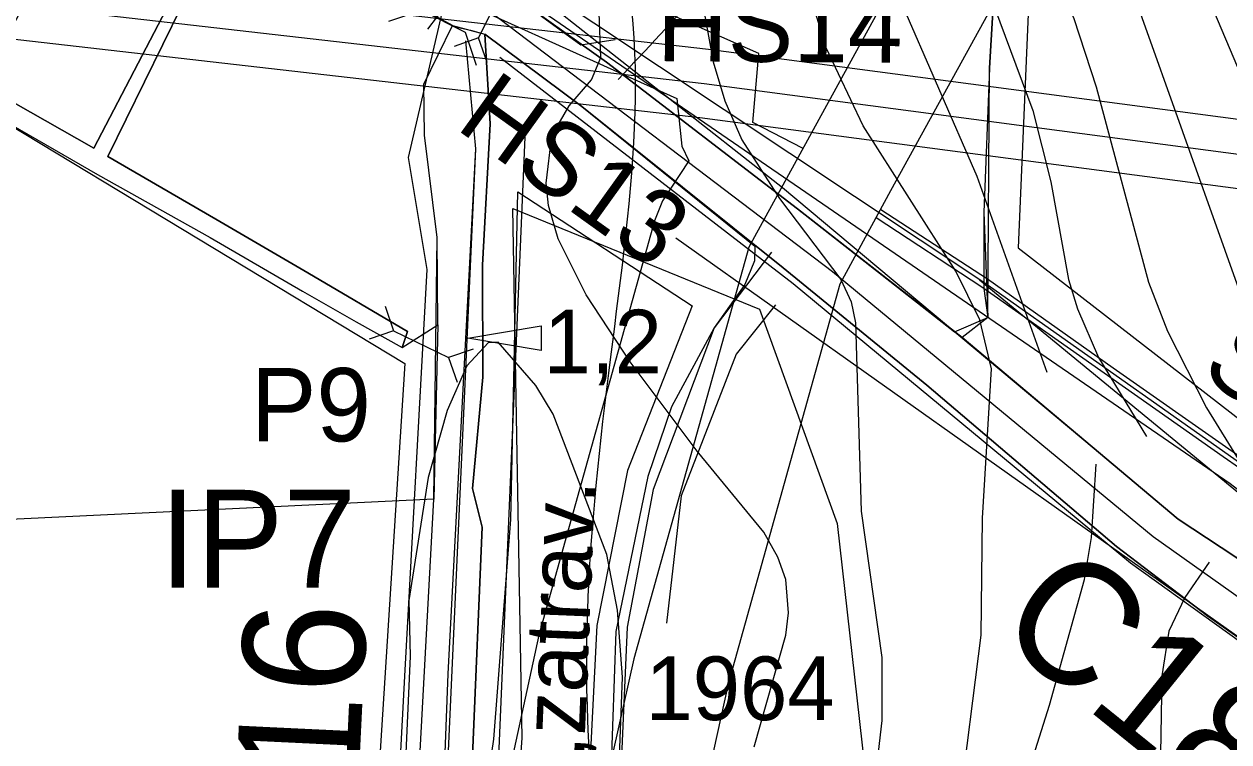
# Model space of a CAD drawing. Extents: x -684583 to -680383, y -1157874 to -1154904.
# Drawn here: x -683041.8 to -682795.6, y -1157173.5 to -1157026.8 of the extents above; entities that cross this region are included whole.
import ezdxf

# ---------------------------------------------------------------- set-up
doc = ezdxf.new("R2010")
doc.units = 0
for name, color, linetype in [('01_PRVKY PRŮZKUMU', 7, 'Continuous'), ('01_PRVKY PSZ', 7, 'Continuous'), ('01_VRSTEVNICE', 7, 'Continuous'), ('02_KULTURY NÁVRH', 7, 'Continuous'), ('02_KULTURY STAV', 7, 'Continuous'), ('03_PC_NÁVRH', 7, 'Continuous'), ('03_PC_OBJEKTY_NÁVRH', 7, 'Continuous'), ('03_PC_OBJEKTY_STAV', 7, 'Continuous'), ('03_PC_POPIS_STAV', 7, 'Continuous'), ('03_PC_STAV', 7, 'Continuous'), ('04_ZPF_OP_ORGAN', 7, 'Continuous'), ('05_VHO_MELIORACE', 7, 'Continuous'), ('05_VHO_V_TOK', 7, 'Continuous'), ('06_BIOGEOGRAFIE', 7, 'Continuous'), ('06_ÚSES_IP', 7, 'Continuous'), ('07_ELEKTRO', 7, 'Continuous'), ('07_OCH_P A POPISY TI', 7, 'Continuous'), ('07_PLYNOVOD', 7, 'Continuous'), ('07_VODOVOD', 7, 'Continuous')]:
    doc.layers.add(name, color=color, linetype=linetype)

msp = doc.modelspace()

# ---------------------------------------------------------------- linework, layer by layer
at = {"layer": '01_PRVKY PRŮZKUMU'}
msp.add_lwpolyline([(-683079.01, -1157360), (-683101.29, -1157316.95), (-683114.85, -1157271.95), (-683118.75, -1157234.34), (-683126.76, -1157209.48), (-683135.39, -1157142.69), (-683125.32, -1157092.55), (-683090.58, -1157019.64), (-682963.99, -1157096.18), (-682973.33, -1157242.9), (-682974.69, -1157258.59), (-682742.08, -1157344.31)], dxfattribs=at)
at = {"layer": '01_PRVKY PSZ'}
msp.add_lwpolyline([(-682951.59, -1157030.23), (-682949.58, -1157052.3), (-682959.2, -1157265.52), (-682962.61, -1157285.78), (-682967.05, -1157374.21), (-682960.06, -1157422.81), (-682935.41, -1157484.7), (-682916.27, -1157543.42), (-682905.44, -1157579.25), (-682923.84, -1157669.47), (-682932.49, -1157713.29), (-682940.15, -1157759.63), (-682931.41, -1157813.92)], dxfattribs=at)
at = {"layer": '01_VRSTEVNICE'}
for points in [[(-682847.51, -1156890.14), (-682852.36, -1156911.54), (-682852.5, -1156920.1), (-682851.64, -1156928.65), (-682847.94, -1156945.77), (-682843.51, -1156958.61), (-682823.4, -1157000.55), (-682813.7, -1157024.51), (-682787.74, -1157097.26)], [(-682829.39, -1156891.85), (-682832.67, -1156900.98), (-682834.1, -1156907.83), (-682834.38, -1156923.8), (-682833.24, -1156935.22), (-682831.39, -1156944.34), (-682827.68, -1156955.76), (-682811.13, -1156992.56), (-682800.43, -1157019.95), (-682783.03, -1157061.03)], [(-682866.62, -1156893.42), (-682865.91, -1156914.39), (-682866.91, -1156948.62), (-682866.05, -1156957.75), (-682852.64, -1156998.83), (-682835.67, -1157044.48), (-682831.96, -1157059.03), (-682828.39, -1157079), (-682826.54, -1157084.99), (-682822.26, -1157094.98), (-682812.42, -1157111.1)], [(-682859.35, -1156895.28), (-682860.06, -1156910.68), (-682859.92, -1156928.65), (-682858.78, -1156943.49), (-682855.64, -1156957.18), (-682852.07, -1156969.16), (-682847.08, -1156982.86), (-682835.24, -1157006.82), (-682827.25, -1157025.65), (-682822.69, -1157039.63), (-682811.99, -1157079.57), (-682808.14, -1157089.56), (-682800.15, -1157105.25), (-682793.16, -1157116.66)], [(-682954.57, -1156992.15), (-682947.79, -1156992.56), (-682940.8, -1156990.71), (-682933.52, -1156986.42), (-682927.25, -1156980.58), (-682916.26, -1156967.45), (-682911.7, -1156963.32), (-682907.85, -1156962.75), (-682902.43, -1156968.88), (-682903, -1156977.44), (-682904.85, -1156986), (-682904.71, -1156998.55), (-682903.14, -1157022.51), (-682901, -1157034.5), (-682898.57, -1157042.48), (-682895.15, -1157050.47), (-682887.45, -1157062.46), (-682874.9, -1157079), (-682872.76, -1157083.57), (-682871.9, -1157087.84), (-682870.76, -1157126.36), (-682866.48, -1157156.31), (-682866.48, -1157169.15), (-682867.48, -1157177.43)], [(-682933.95, -1157049.62), (-682930.38, -1157043.48), (-682925.82, -1157038.21), (-682923.96, -1157033.64), (-682924.25, -1157024.51), (-682926.1, -1157019.95), (-682931.1, -1157013.81), (-682939.08, -1157010.53), (-682943.08, -1157009.68), (-682948.21, -1157009.53), (-682955.06, -1157011.67), (-682959.77, -1157017.09), (-682960.34, -1157019.52), (-682963.33, -1157020.95), (-682976.6, -1157023.08)], [(-682850.79, -1157187.7), (-682846.22, -1157151.75), (-682845.94, -1157127.79), (-682844.08, -1157097.26), (-682846.51, -1157087.28), (-682851.36, -1157077.29), (-682870.33, -1157047.62), (-682877.89, -1157031.64), (-682882.74, -1157015.67)], [(-682862.77, -1157021.94), (-682847.08, -1157057.89), (-682832.82, -1157097.97)], [(-682892.58, -1157174.57), (-682886.16, -1157151.75), (-682885.59, -1157147.18), (-682886.16, -1157140.34), (-682887.73, -1157135.77), (-682890.59, -1157130.64), (-682904.28, -1157114.09), (-682917.97, -1157095.83), (-682926.96, -1157082.14), (-682932.67, -1157070.73), (-682934.66, -1157063.88), (-682935.09, -1157059.32), (-682933.95, -1157049.62)], [(-682920.83, -1157194.54), (-682919.54, -1157160.31), (-682920.54, -1157146.61), (-682922.68, -1157135.2), (-682933.67, -1157106.53), (-682937.23, -1157100.68), (-682944.93, -1157091.84), (-682946.93, -1157091.98), (-682951.35, -1157096.69), (-682955.35, -1157105.82), (-682959.2, -1157119.51), (-682963.19, -1157144.62), (-682962.91, -1157156.03), (-682963.91, -1157178.85)], [(-682738.53, -1157332.19), (-682758.5, -1157324.21), (-682773.19, -1157316.5), (-682784.17, -1157309.37), (-682808.42, -1157289.97), (-682831.1, -1157274.57), (-682841.37, -1157264.44), (-682846.22, -1157255.31), (-682847.65, -1157250.74), (-682848.22, -1157246.18), (-682848.08, -1157234.91), (-682846.65, -1157224.78), (-682840.09, -1157190.83), (-682832.24, -1157166.01), (-682825.11, -1157140.34), (-682823.69, -1157131.78), (-682822.69, -1157116.8)], [(-682799.58, -1157136.77), (-682804.57, -1157144.05), (-682807.85, -1157150.89), (-682809.28, -1157160.02), (-682809.56, -1157176), (-682810.7, -1157185.13), (-682813.27, -1157196.54), (-682821.12, -1157221.64), (-682822.26, -1157232.77), (-682822.02, -1157238.59), (-682819.55, -1157246.46), (-682815.55, -1157253.74), (-682810.13, -1157259.73), (-682801.72, -1157266.86), (-682782.18, -1157285.26), (-682759.92, -1157300.1), (-682734.25, -1157315.08), (-682719.41, -1157321.21), (-682697.45, -1157326.92)]]:
    msp.add_lwpolyline(points, dxfattribs=at)
at = {"layer": '02_KULTURY NÁVRH'}
msp.add_lwpolyline([(-682950.17, -1157176.38), (-682948.21, -1157129.67), (-682950.13, -1157121.77), (-682948.08, -1157098.95), (-682948.13, -1157076.07), (-682946.56, -1157047.16), (-682947.67, -1157028.84), (-682927.83, -1157043.62), (-682892.47, -1157072.21), (-682892.51, -1157075.22), (-682894.49, -1157080.03), (-682900.8, -1157088.89), (-682909.46, -1157105.07), (-682914.36, -1157119.31), (-682920.86, -1157150.94), (-682925.66, -1157286.45)], dxfattribs=at)
at = {"layer": '02_KULTURY STAV'}
for points in [[(-682792.62, -1156514.96), (-682796.58, -1156536.16), (-682796.03, -1156549.68), (-682795.1, -1156567.41), (-682795.87, -1156587.1), (-682800.74, -1156607.7), (-682805.25, -1156630.03), (-682808.53, -1156661.75), (-682809.42, -1156675.8), (-682811.51, -1156694.23), (-682814.12, -1156742.41), (-682814.76, -1156765.27), (-682825.52, -1156817.11), (-682826.23, -1156835.78), (-682833.65, -1156897.15), (-682841.03, -1156977.03), (-682844.53, -1157035.81), (-682845.68, -1157065.25), (-682844.82, -1157086.77), (-682850.09, -1157090.88), (-682805.97, -1157127.99), (-682750, -1157164.87)], [(-682833.65, -1156897.15), (-682841.03, -1156977.03), (-682844.53, -1157035.81), (-682845.68, -1157065.25), (-682845.68, -1157080.84), (-682844.82, -1157086.77), (-682850.09, -1157090.88), (-682883.77, -1157064.59), (-682922.79, -1157034.61), (-682937.14, -1157024.36), (-682916.7, -1156994.23), (-682909.51, -1156993.03), (-682901.87, -1156985.12), (-682891.29, -1156967.88), (-682886.04, -1156970.38), (-682879.39, -1156972.45), (-682883.26, -1156983.81), (-682881.57, -1156983.38), (-682877.08, -1156976.67), (-682874.97, -1156971.91), (-682871.59, -1156959.54), (-682861.19, -1156933.96), (-682850.61, -1156904.16), (-682845.6, -1156883.82)], [(-682792.27, -1157137.15), (-682805.97, -1157127.99), (-682850.09, -1157090.88), (-682883.77, -1157064.59), (-682922.79, -1157034.61), (-682937.14, -1157024.36), (-682955.51, -1157012.45), (-682965.71, -1157007.37), (-682979.82, -1156999.75), (-683040.73, -1156970.35), (-683056.67, -1156957.12)], [(-683061.29, -1156975.68), (-682991.45, -1157007.74), (-682963.23, -1157022.34), (-682954.24, -1157027.11), (-682953.02, -1157027.48), (-682950.58, -1157028.02), (-682947.67, -1157028.84), (-682927.83, -1157043.62), (-682886.7, -1157076.63), (-682857.33, -1157100.64), (-682818.58, -1157133.57), (-682799.92, -1157147.75), (-682755.75, -1157178.87)], [(-683044.54, -1157047.31), (-683026.78, -1157057.53), (-683003.8, -1157070.41), (-682984.94, -1157081.43), (-682973.97, -1157087.66), (-682964.52, -1157092.89), (-682963.47, -1157089.67), (-682983.84, -1157077.66), (-683002.59, -1157066.71), (-683024.71, -1157053.87), (-683009.7, -1157023.34), (-683011.98, -1157022.24), (-683027.52, -1157052.19), (-683050.51, -1157039.17), (-683029.14, -1156998.86), (-683031.38, -1156997.74), (-683034.85, -1157002.94), (-683040.33, -1157014.68), (-683053.23, -1157037.54)], [(-683050.51, -1157039.17), (-683027.52, -1157052.19), (-683011.98, -1157022.24)], [(-683009.7, -1157023.34), (-683024.71, -1157053.87), (-683002.59, -1157066.71), (-682983.84, -1157077.66), (-682963.47, -1157089.67), (-682964.52, -1157092.89), (-682957.27, -1157088.26), (-682957.4, -1157070.42), (-682960, -1157049.53), (-682960.13, -1157039.09), (-682954.24, -1157027.11), (-682958.63, -1157024.72)], [(-682961.95, -1157195.51), (-682958.06, -1157123.89), (-682957.4, -1157070.42), (-682960, -1157049.53), (-682960.13, -1157039.09), (-682954.24, -1157027.11), (-682947.67, -1157028.84), (-682946.56, -1157047.16), (-682948.13, -1157076.07), (-682948.08, -1157098.95), (-682950.13, -1157121.77), (-682948.21, -1157129.67), (-682950.17, -1157176.38)], [(-682755.75, -1157178.87), (-682799.92, -1157147.75), (-682818.58, -1157133.57), (-682857.33, -1157100.64), (-682886.7, -1157076.63), (-682927.83, -1157043.62), (-682947.67, -1157028.84), (-682946.56, -1157047.16), (-682948.13, -1157076.07), (-682948.08, -1157098.95), (-682950.13, -1157121.77), (-682948.21, -1157129.67), (-682950.17, -1157176.38), (-682953.36, -1157198.73), (-682938.6, -1157212.34), (-682936.57, -1157222.08), (-682940.25, -1157238.24), (-682955.19, -1157266.56), (-682959.55, -1157286.97), (-682959.34, -1157293.71), (-682952.5, -1157293.15), (-682878.23, -1157311.8), (-682748.43, -1157354.76)]]:
    msp.add_lwpolyline(points, dxfattribs=at)
for points in [[(-683104.87, -1157044.75), (-683097.43, -1157031.94), (-683090.58, -1157019.64), (-683072.43, -1156988.22), (-683068.4, -1156989.49), (-683064.02, -1156992.6), (-683069.65, -1157008.14), (-683071.62, -1157014.89), (-683071.88, -1157022.44), (-683071.15, -1157028.51), (-683069.3, -1157031.54), (-683062.84, -1157036.11), (-683044.54, -1157047.31), (-683026.78, -1157057.53), (-683003.8, -1157070.41), (-682984.94, -1157081.43), (-682973.97, -1157087.66), (-682964.52, -1157092.89), (-682957.27, -1157088.26), (-682958.06, -1157123.89), (-683092.93, -1157130.42), (-683091.87, -1157124.45), (-683095.49, -1157062.13), (-683100.2, -1157050.38)], [(-683092.93, -1157130.42), (-683106.43, -1157165.69), (-683118.57, -1157201.97), (-683120.22, -1157223.29), (-683120.73, -1157236.27), (-683120.05, -1157251.32), (-683117.34, -1157269.31), (-683109.5, -1157295.71), (-683104.67, -1157310.58), (-683097.47, -1157329.16), (-683089.13, -1157345.4), (-683079.01, -1157360), (-683060.22, -1157384.58), (-683050.32, -1157398.08), (-682970.5, -1157367.3), (-682967.98, -1157337.6), (-682967.71, -1157306.5), (-682965.68, -1157276.1), (-682963.63, -1157251.67), (-682961.95, -1157195.51), (-682958.06, -1157123.89)]]:
    msp.add_lwpolyline(points, close=True, dxfattribs=at)
at = {"layer": '03_PC_NÁVRH'}
msp.add_lwpolyline([(-682889.04, -1157073.4), (-682900.8, -1157088.89), (-682913.24, -1157121.94), (-682918.55, -1157150.08), (-682924.35, -1157282.04), (-682919.84, -1157295.45), (-682909, -1157302.49), (-682878.23, -1157311.8), (-682748.43, -1157354.76), (-682691.27, -1157360.9), (-682632.76, -1157364.86), (-682566.31, -1157368.27), (-682540.68, -1157375.39)], dxfattribs=at)
at = {"layer": '03_PC_OBJEKTY_NÁVRH'}
for points in [[(-682675.61, -1157221.62), (-682750, -1157164.87), (-682805.97, -1157127.99), (-682886.81, -1157060.31), (-682934.61, -1157022.63)], [(-682680.1, -1157237.27), (-682725.73, -1157201.62), (-682815.68, -1157136.98), (-682884.63, -1157079.88), (-682944.6, -1157033.65)], [(-682888.24, -1157084.22), (-682896.26, -1157094.25), (-682907.51, -1157123.22), (-682910.54, -1157149.24)]]:
    msp.add_lwpolyline(points, dxfattribs=at)
at = {"layer": '03_PC_OBJEKTY_STAV'}
for points in [[(-682943.43, -1157018.4), (-682948.91, -1157029.64)], [(-682921.03, -1157030.03), (-682928.01, -1157031.11), (-682936.09, -1157025.22), (-682937.18, -1157018.23)], [(-682967.28, -1157026.2), (-682960.57, -1157023.98), (-682951.63, -1157028.48), (-682949.42, -1157035.19)], [(-682947.19, -1157034.65), (-682948.91, -1157029.64), (-682953.93, -1157031.36)], [(-682968, -1157084.5), (-682966.28, -1157089.51), (-682971.29, -1157091.24)], [(-682966.28, -1157089.51), (-682955.04, -1157094.99)], [(-682950.03, -1157093.27), (-682955.04, -1157094.99), (-682953.32, -1157100.01)]]:
    msp.add_lwpolyline(points, dxfattribs=at)
at = {"layer": '03_PC_STAV'}
for points in [[(-683066.01, -1156961.87), (-682948.18, -1157023.01), (-682876.6, -1157077.37), (-682811.04, -1157131.53), (-682733.64, -1157186.49), (-682671.49, -1157234.52)], [(-682956.44, -1157024.49), (-682963.29, -1157054.08), (-682959.47, -1157076.95), (-682964.05, -1157160.08), (-682974.97, -1157364.97), (-682973.09, -1157394), (-682966.3, -1157425.87), (-682936.61, -1157496.14), (-682917.8, -1157562.99), (-682910.6, -1157586.57), (-682939.66, -1157707.13), (-682946.26, -1157762.29), (-682942.96, -1157791.01), (-682939.8, -1157807.76), (-682935.77, -1157818.43)]]:
    msp.add_lwpolyline(points, dxfattribs=at)
at = {"layer": '04_ZPF_OP_ORGAN'}
for points in [[(-682779.67, -1156436.1), (-682794.2, -1156466.69), (-682788.61, -1156477.13), (-682784.14, -1156488.69), (-682785.65, -1156500.47), (-682788.37, -1156536.68), (-682784.46, -1156588.73), (-682797.19, -1156641.23), (-682810.23, -1156775.49), (-682822.53, -1156859.77), (-682834.09, -1156965.69), (-682838.67, -1157072.57), (-682735.79, -1157152.27), (-682675.08, -1157204.91), (-682675.48, -1157169.72), (-682684.88, -1157129.04), (-682735.36, -1157001.81), (-682708.95, -1156906.13), (-682698.09, -1156909.32), (-682682.43, -1156889.14), (-682649.29, -1156744.14), (-682652.93, -1156622.47), (-682648.88, -1156555.77), (-682641, -1156504.41)], [(-682940.92, -1157061.11), (-682905.24, -1157084.42), (-682918.46, -1157118.08), (-682924.74, -1157149.74), (-682931.48, -1157283.63), (-682925.27, -1157296.3), (-682956.65, -1157288.82), (-682952.11, -1157268.38), (-682933.28, -1157228.3), (-682935.29, -1157211.33), (-682949.31, -1157196.77), (-682945.83, -1157172.99), (-682942.36, -1157128.1)]]:
    msp.add_lwpolyline(points, close=True, dxfattribs=at)
at = {"layer": '05_VHO_MELIORACE'}
msp.add_lwpolyline([(-682941.91, -1157064.51), (-682891.52, -1157085.05), (-682875.65, -1157128.92), (-682870.05, -1157178.4), (-682916.71, -1157177.46), (-682944.71, -1157238.14), (-682940.04, -1157172.8)], close=True, dxfattribs=at)
at = {"layer": '05_VHO_V_TOK'}
msp.add_lwpolyline([(-682951.59, -1157030.23), (-682949.58, -1157052.3), (-682955.19, -1157159.61), (-682959.2, -1157265.52), (-682962.61, -1157285.78), (-682965.51, -1157340.18)], dxfattribs=at)
msp.add_lwpolyline([(-682936.12, -1157088.51), (-682936.12, -1157093.51), (-682951.12, -1157091.01)], close=True, dxfattribs=at)
at = {"layer": '06_BIOGEOGRAFIE'}
for points in [[(-682820.52, -1156443.86), (-682794.69, -1156436.97), (-682777.47, -1156454.19), (-682792.96, -1156667.78), (-682801.57, -1156726.35), (-682792.96, -1156755.63), (-682811.91, -1156802.14), (-682839.46, -1156886.54), (-682887.67, -1157000.23), (-682920.39, -1157038.12)], [(-683605.53, -1156693.94), (-683552.15, -1156773.17), (-683505.66, -1156862.74), (-683385.12, -1156876.52), (-683240.48, -1156867.91), (-682983.91, -1156935.09), (-682923.69, -1156998.38), (-682921.97, -1157094.84), (-682923.69, -1157198.19), (-682892.7, -1157272.26), (-682746.33, -1157329.1), (-682572.41, -1157337.72), (-682417.44, -1157289.49), (-682386.73, -1157266.62)], [(-683662.04, -1156787.77), (-683658.6, -1156877.34), (-683631.05, -1156927.29), (-683541.5, -1156975.52), (-683489.85, -1157028.92), (-683414.08, -1157027.2), (-683362.42, -1157025.48), (-683360.7, -1157063.37), (-683464.02, -1157132.27), (-683493.29, -1157163.28), (-683474.35, -1157189.11), (-683407.19, -1157171.89), (-683317.65, -1157115.05), (-683269.44, -1157104.71), (-683207.44, -1157173.61), (-683186.78, -1157259.74), (-683105.85, -1157416.48), (-683069.69, -1157530.17), (-683073.13, -1157580.12), (-683097.24, -1157628.35), (-683264.27, -1157657.63), (-683431.3, -1157647.3), (-683531.17, -1157605.96), (-683636.21, -1157542.23), (-683651.71, -1157521.56), (-683682.7, -1157519.83), (-683708.53, -1157528.45), (-683818.74, -1157547.39), (-683870.4, -1157518.11), (-683980.6, -1157521.56), (-684052.92, -1157490.55), (-684171.74, -1157400.98), (-684213.07, -1157375.14), (-684250.95, -1157388.92), (-684249.23, -1157437.15), (-684237.17, -1157466.44), (-684170.02, -1157518.11), (-684097.7, -1157562.9), (-684011.6, -1157605.96), (-683953.05, -1157602.51), (-683891.06, -1157626.63), (-683835.96, -1157619.74), (-683789.47, -1157599.07), (-683713.7, -1157578.4), (-683625.88, -1157592.18), (-683551.84, -1157667.97), (-683445.07, -1157736.87), (-683346.92, -1157771.32), (-683179.89, -1157767.87), (-683081.74, -1157773.04), (-683016.71, -1157810.65), (-682999.16, -1157844)]]:
    msp.add_spline(points, degree=3, dxfattribs=at)
at = {"layer": '06_ÚSES_IP'}
for points in [[(-682860.06, -1156892.14), (-682891.29, -1156967.88), (-682901.87, -1156985.12), (-682909.51, -1156993.03), (-682916.7, -1156994.23), (-682937.14, -1157024.36), (-682922.79, -1157034.61), (-682883.77, -1157064.59), (-682851.66, -1157089.7), (-682844.82, -1157086.77), (-682844.53, -1157035.81), (-682841.03, -1156977.03), (-682826.23, -1156835.78)], [(-682939.38, -1157048.27), (-682948.96, -1157272.77)], [(-682908.61, -1157070.47), (-682716.68, -1157206.67), (-682614.03, -1157315.66), (-682562.58, -1157361.57)], [(-682846.57, -1157079.05), (-682752.11, -1157156.72), (-682652.87, -1157228.38), (-682558.55, -1157329.78), (-682523.24, -1157351.98)]]:
    msp.add_lwpolyline(points, dxfattribs=at)
at = {"layer": '07_ELEKTRO'}
msp.add_lwpolyline([(-683073.5, -1157019.42), (-682902.81, -1157038.95), (-682625.19, -1157075.68)], dxfattribs=at)
at = {"layer": '07_OCH_P A POPISY TI'}
for p, q in [((-682901.95, -1157032), (-683063.13, -1157013.56)), ((-682957.22, -1157019.98), (-682921.25, -1157036.19)), ((-682864.64, -1157060.79), (-682842.16, -1157019.9)), ((-683068.97, -1157026.98), (-682903.67, -1157045.9)), ((-682624.27, -1157068.74), (-682901.95, -1157032)), ((-682921.25, -1157036.19), (-682908.38, -1157041.99)), ((-682908.38, -1157041.99), (-682907.4, -1157051.79)), ((-682903.67, -1157045.9), (-682626.11, -1157082.62)), ((-682907.4, -1157051.79), (-682905.95, -1157054.74)), ((-682905.95, -1157054.74), (-682911.3, -1157062.92)), ((-682875.03, -1157079.92), (-682864.64, -1157060.79)), ((-682911.3, -1157062.92), (-682912.95, -1157067.02)), ((-682846.04, -1157080.56), (-682867.67, -1157066.38)), ((-682866.69, -1157064.69), (-682844.92, -1157078.9)), ((-682912.95, -1157067.02), (-682936.62, -1157151.75)), ((-682844.92, -1157078.9), (-682819.2, -1157097.05)), ((-682897.78, -1157161.37), (-682875.03, -1157079.92)), ((-682796.72, -1157115.27), (-682846.04, -1157080.56)), ((-682819.2, -1157097.05), (-682795.58, -1157113.63)), ((-682795.58, -1157113.63), (-682771.42, -1157130.57)), ((-682772.58, -1157132.21), (-682796.72, -1157115.27)), ((-682936.62, -1157151.75), (-682957.15, -1157246.18)), ((-682921.93, -1157271.6), (-682897.78, -1157161.37))]:
    msp.add_line(p, q, dxfattribs=at)
at = {"layer": '07_PLYNOVOD'}
for points in [[(-682369.73, -1156748.62), (-682856.97, -1157005.33), (-682893.69, -1157072.4), (-682917.2, -1157156.56), (-682941.77, -1157266.45), (-682978.36, -1157266.27), (-682983.87, -1157423.53), (-682924.91, -1157585.64), (-682996.21, -1157612), (-683026.05, -1157750.31), (-683062.69, -1157756.02), (-683074.55, -1157765.36), (-683106.38, -1157774.6)], [(-683147.01, -1156952.11), (-683137.67, -1156959.94), (-683133.31, -1156965.24), (-683117.07, -1156969.63), (-683111.6, -1156967.36), (-683104.51, -1156969.61), (-683100.04, -1156971.88), (-683094.9, -1156975.24), (-683072.81, -1156986.32), (-683066.71, -1156988.26), (-683055.41, -1156989.46), (-683050.72, -1156987.03), (-683044.94, -1156988.52), (-683029.06, -1156994.95), (-682996.03, -1157009.58), (-682968.18, -1157022.59), (-682967.22, -1157019.85), (-682961.95, -1157008.21), (-682947.77, -1157013.15), (-682938.57, -1157017.66), (-682845.48, -1157079.73), (-682740.19, -1157153.94), (-682703.61, -1157187.85), (-682654.74, -1157227.72)], [(-682882.73, -1157052.19), (-682892.85, -1157046.94), (-682891.62, -1157032.79), (-682957.83, -1157003.5)]]:
    msp.add_lwpolyline(points, dxfattribs=at)
at = {"layer": '07_VODOVOD'}
msp.add_lwpolyline([(-682959.31, -1157027.82), (-682949.41, -1157014.81), (-682795.34, -1157120.72), (-682713.54, -1157183.93), (-682627.78, -1157260.58)], dxfattribs=at)

# ---------------------------------------------------------------- texts
at = {"layer": '03_PC_OBJEKTY_STAV'}
for s, rotation, p in [('HS14', 359.597, (-682912.51, -1157034.37)), ('HS13', 324.3369, (-682953.88, -1157048.03))]:
    msp.add_text(s, height=15, rotation=rotation, dxfattribs=at).set_placement(p)
msp.add_text('P9', height=15, dxfattribs=at).set_placement((-682995.45, -1157112.11))
at = {"layer": '03_PC_POPIS_STAV'}
for s, rotation, p in [('C18', 321.0885, (-682844.04, -1157151.12)), ('C16', 87.2662, (-682974.64, -1157206.88))]:
    msp.add_text(s, height=25, rotation=rotation, dxfattribs=at).set_placement(p)
at = {"layer": '04_ZPF_OP_ORGAN'}
msp.add_text('PEO2,zatrav.', height=13, rotation=87.6563, dxfattribs=at).set_placement((-682929.29, -1157223.44))
at = {"layer": '05_VHO_MELIORACE'}
msp.add_text('1964', height=13, dxfattribs=at).set_placement((-682914.83, -1157169.08))
at = {"layer": '05_VHO_V_TOK'}
msp.add_text('1,2', height=13, dxfattribs=at).set_placement((-682935.62, -1157098.2))
at = {"layer": '06_ÚSES_IP'}
msp.add_text('IP7', height=20, dxfattribs=at).set_placement((-683014.08, -1157142.01))
at = {"layer": '07_OCH_P A POPISY TI'}
msp.add_text('STL plynovod', height=15, rotation=322.4304, dxfattribs=at).set_placement((-682801.69, -1157097.97))

doc.saveas('drawing.dxf')
